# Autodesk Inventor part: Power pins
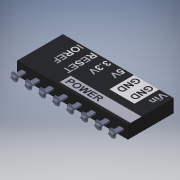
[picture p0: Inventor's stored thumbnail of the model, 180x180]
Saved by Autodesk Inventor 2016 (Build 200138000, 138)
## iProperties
Created: 2018-03
Part Number: Power pins
Material: Générique
Document SubType Name: Modeling
Designer: Bruno
Density: 1 g/cm^3
Appearance: Par défaut
Author: Bruno
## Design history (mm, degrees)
feature "Composite1"
body "Srf1"
